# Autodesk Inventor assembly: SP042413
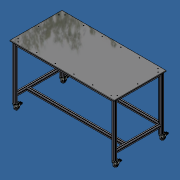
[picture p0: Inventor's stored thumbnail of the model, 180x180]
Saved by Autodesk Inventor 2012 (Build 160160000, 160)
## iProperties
Created: 2013-04
Part Number: SP042413
Document SubType Name: Assembly
Designer: Admin
Author: Admin
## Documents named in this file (7)
- C:\Andys Backup Data\ANDY'S INVENTOR\INVENTOR LIBRARIES\ASSEMBLY LIBRARY\45 SERIES\TABLES_CARTS\SP042413 45X45UL\SP042413 MAIN ASSY.iam
- C:\Andys Backup Data\ANDY'S INVENTOR\INVENTOR LIBRARIES\ASSEMBLY LIBRARY\45 SERIES\TABLES_CARTS\SP042413 45X45UL\SP042413 LEG ASSY.iam
- C:\Andys Backup Data\ANDY'S INVENTOR\INVENTOR LIBRARIES\ASSEMBLY LIBRARY\45 SERIES\TABLES_CARTS\SP042413 45X45UL\SP042413 HORI WIDTH.ipt
- C:\Andys Backup Data\ANDY'S INVENTOR\INVENTOR LIBRARIES\ASSEMBLY LIBRARY\45 SERIES\TABLES_CARTS\SP042413 45X45UL\SP042413 HORI DEPTH.ipt
- C:\Andys Backup Data\ANDY'S INVENTOR\INVENTOR LIBRARIES\ASSEMBLY LIBRARY\45 SERIES\TABLES_CARTS\SP042413 45X45UL\SP042413 TABLE TOP.ipt
- C:\Andys Backup Data\ANDY'S INVENTOR\INVENTOR LIBRARIES\PARTS LIBRARY\FASTENING ELEMENTS\SCREWS COUNTERSUNK\21.1566_9 M6X25 CSUNK BLACK.IPT
- C:\Andys Backup Data\ANDY'S INVENTOR\INVENTOR LIBRARIES\PARTS LIBRARY\FASTENING ELEMENTS\NUTS\21.1330_2 M6 SQUARE NUT POS FXG.ipt
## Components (50 placed, 6 different names)
1. SP042413 LEG ASSY:1 [sub-assembly] — Mate:1, Flush:1, Flush:2, Mate:2, Flush:3, Flush:4, Flush:22
2. SP042413 HORI WIDTH:1 — Mate:1, Flush:1, Flush:2, Mate:16
3. SP042413 HORI DEPTH:1 — Mate:2, Flush:3, Flush:4, Mate:3, Flush:5, Flush:6, Mate:14
4. SP042413 LEG ASSY:2 [sub-assembly] — Mate:3, Flush:5, Flush:6, Mate:4, Flush:7, Flush:8, Mate:9, Mate:10, Flush:17, Flush:24
5. SP042413 HORI WIDTH:2 — Mate:4, Flush:7, Flush:8, Mate:5, Flush:9, Flush:10, Mate:11, Flush:20, Mate:12
6. SP042413 LEG ASSY:3 [sub-assembly] — Mate:5, Flush:9, Flush:10, Mate:6, Flush:11, Flush:12, Mate:8, Flush:15
7. SP042413 HORI DEPTH:2 — Mate:6, Flush:11, Flush:12, Mate:7, Flush:13, Flush:14, Mate:15
8. SP042413 LEG ASSY:4 [sub-assembly] — Mate:7, Flush:13, Flush:14
9. SP042413 HORI DEPTH:3 — Mate:8, Flush:15, Flush:23
10. SP042413 HORI WIDTH:3 — Mate:9, Flush:18, Flush:24
11. SP042413 HORI DEPTH:4 — Mate:10, Flush:17, Flush:18, Mate:13, Flush:21
12. SP042413 HORI DEPTH:5 — Mate:11, Flush:20, Mate:12
13. SP042413 HORI WIDTH:4 — Mate:13, Flush:21, Flush:22, Flush:23
14. SP042413 TABLE TOP:1 — Mate:14, Mate:15, Mate:16, Insert:1, Insert:2, Insert:3, Insert:4, Insert:5, Insert:6, Insert:7, Insert:8, Insert:9, Insert:10, Insert:11, Insert:12, Insert:13, Insert:14, Insert:15, Insert:16, Insert:17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
15. 21.1566/9 M6x25 C'SUNK BLACK:1 — Insert:3
16. 21.1566/9 M6x25 C'SUNK BLACK:2 — Insert:4
17. 21.1566/9 M6x25 C'SUNK BLACK:3 — Insert:5
18. 21.1566/9 M6x25 C'SUNK BLACK:4 — Insert:6
19. 21.1566/9 M6x25 C'SUNK BLACK:5 — Insert:7
20. 21.1566/9 M6x25 C'SUNK BLACK:6 — Insert:8
21. 21.1566/9 M6x25 C'SUNK BLACK:7 — Insert:9
22. 21.1566/9 M6x25 C'SUNK BLACK:8 — Insert:10
23. 21.1566/9 M6x25 C'SUNK BLACK:9 — Insert:11
24. 21.1566/9 M6x25 C'SUNK BLACK:10 — Insert:12
25. 21.1566/9 M6x25 C'SUNK BLACK:11 — Insert:13
26. 21.1566/9 M6x25 C'SUNK BLACK:12 — Insert:14
27. 21.1566/9 M6x25 C'SUNK BLACK:13 — Insert:15
28. 21.1566/9 M6x25 C'SUNK BLACK:14 — Insert:16
29. 21.1566/9 M6x25 C'SUNK BLACK:15 — Insert:17
30. 21.1566/9 M6x25 C'SUNK BLACK:16 — Insert:18
31. 21.1566/9 M6x25 C'SUNK BLACK:17 — Insert:1
32. 21.1566/9 M6x25 C'SUNK BLACK:18 — Insert:2
33. 21.1330_2 M6 SQUARE NUT POS FXG:1 — Insert:24, Angle:13
34. 21.1330_2 M6 SQUARE NUT POS FXG:2 — Insert:23, Angle:14
35. 21.1330_2 M6 SQUARE NUT POS FXG:3 — Insert:22, Angle:15
36. 21.1330_2 M6 SQUARE NUT POS FXG:4 — Insert:21, Angle:16
37. 21.1330_2 M6 SQUARE NUT POS FXG:5 — Insert:19
38. 21.1330_2 M6 SQUARE NUT POS FXG:6 — Insert:20
39. 21.1330_2 M6 SQUARE NUT POS FXG:7 — Insert:25, Angle:12
40. 21.1330_2 M6 SQUARE NUT POS FXG:8 — Insert:26, Angle:11
41. 21.1330_2 M6 SQUARE NUT POS FXG:9 — Insert:27, Angle:10
42. 21.1330_2 M6 SQUARE NUT POS FXG:10 — Insert:28, Angle:9
43. 21.1330_2 M6 SQUARE NUT POS FXG:11 — Insert:29, Angle:8
44. 21.1330_2 M6 SQUARE NUT POS FXG:12 — Insert:30, Angle:7
45. 21.1330_2 M6 SQUARE NUT POS FXG:13 — Insert:31, Angle:6
46. 21.1330_2 M6 SQUARE NUT POS FXG:14 — Insert:32, Angle:5
47. 21.1330_2 M6 SQUARE NUT POS FXG:15 — Insert:33, Angle:4
48. 21.1330_2 M6 SQUARE NUT POS FXG:16 — Insert:36, Angle:1
49. 21.1330_2 M6 SQUARE NUT POS FXG:17 — Insert:35, Angle:2
50. 21.1330_2 M6 SQUARE NUT POS FXG:18 — Insert:34, Angle:3
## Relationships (90: Insert 36, Flush 22, Mate 16, Angle 16)
- Mate:1: SP042413 LEG ASSY:1 ↔ SP042413 HORI WIDTH:1
- Flush:1: SP042413 LEG ASSY:1 ↔ SP042413 HORI WIDTH:1
- Flush:2: SP042413 LEG ASSY:1 ↔ SP042413 HORI WIDTH:1
- Mate:2: SP042413 LEG ASSY:1 ↔ SP042413 HORI DEPTH:1
- Flush:3: SP042413 LEG ASSY:1 ↔ SP042413 HORI DEPTH:1
- Flush:4: SP042413 LEG ASSY:1 ↔ SP042413 HORI DEPTH:1
- Mate:3: SP042413 HORI DEPTH:1 ↔ SP042413 LEG ASSY:2
- Flush:5: SP042413 HORI DEPTH:1 ↔ SP042413 LEG ASSY:2
- Flush:6: SP042413 HORI DEPTH:1 ↔ SP042413 LEG ASSY:2
- Mate:4: SP042413 LEG ASSY:2 ↔ SP042413 HORI WIDTH:2
- Flush:7: SP042413 LEG ASSY:2 ↔ SP042413 HORI WIDTH:2
- Flush:8: SP042413 LEG ASSY:2 ↔ SP042413 HORI WIDTH:2
- Mate:5: SP042413 HORI WIDTH:2 ↔ SP042413 LEG ASSY:3
- Flush:9: SP042413 HORI WIDTH:2 ↔ SP042413 LEG ASSY:3
- Flush:10: SP042413 HORI WIDTH:2 ↔ SP042413 LEG ASSY:3
- Mate:6: SP042413 LEG ASSY:3 ↔ SP042413 HORI DEPTH:2
- Flush:11: SP042413 LEG ASSY:3 ↔ SP042413 HORI DEPTH:2
- Flush:12: SP042413 LEG ASSY:3 ↔ SP042413 HORI DEPTH:2
- Mate:7: SP042413 HORI DEPTH:2 ↔ SP042413 LEG ASSY:4
- Flush:13: SP042413 HORI DEPTH:2 ↔ SP042413 LEG ASSY:4
- Flush:14: SP042413 HORI DEPTH:2 ↔ SP042413 LEG ASSY:4
- Mate:8: SP042413 LEG ASSY:3 ↔ SP042413 HORI DEPTH:3
- Flush:15: SP042413 LEG ASSY:3 ↔ SP042413 HORI DEPTH:3
- Mate:9: SP042413 LEG ASSY:2 ↔ SP042413 HORI WIDTH:3
- Mate:10: SP042413 LEG ASSY:2 ↔ SP042413 HORI DEPTH:4
- Flush:17: SP042413 LEG ASSY:2 ↔ SP042413 HORI DEPTH:4
- Flush:18: SP042413 HORI WIDTH:3 ↔ SP042413 HORI DEPTH:4
- Mate:11: SP042413 HORI WIDTH:2 ↔ SP042413 HORI DEPTH:5
- Flush:20: SP042413 HORI WIDTH:2 ↔ SP042413 HORI DEPTH:5
- Mate:12: SP042413 HORI WIDTH:2 ↔ SP042413 HORI DEPTH:5
- Mate:13: SP042413 HORI DEPTH:4 ↔ SP042413 HORI WIDTH:4
- Flush:21: SP042413 HORI DEPTH:4 ↔ SP042413 HORI WIDTH:4
- Flush:22: SP042413 LEG ASSY:1 ↔ SP042413 HORI WIDTH:4
- Flush:23: SP042413 HORI DEPTH:3 ↔ SP042413 HORI WIDTH:4
- Mate:14: SP042413 HORI DEPTH:1 ↔ SP042413 TABLE TOP:1
- Mate:15: SP042413 HORI DEPTH:2 ↔ SP042413 TABLE TOP:1
- Mate:16: SP042413 HORI WIDTH:1 ↔ SP042413 TABLE TOP:1
- Insert:1: SP042413 TABLE TOP:1 ↔ 21.1566/9 M6x25 C'SUNK BLACK:17
- Insert:2: SP042413 TABLE TOP:1 ↔ 21.1566/9 M6x25 C'SUNK BLACK:18
- Insert:3: SP042413 TABLE TOP:1 ↔ 21.1566/9 M6x25 C'SUNK BLACK:1
- Insert:4: SP042413 TABLE TOP:1 ↔ 21.1566/9 M6x25 C'SUNK BLACK:2
- Insert:5: SP042413 TABLE TOP:1 ↔ 21.1566/9 M6x25 C'SUNK BLACK:3
- Insert:6: SP042413 TABLE TOP:1 ↔ 21.1566/9 M6x25 C'SUNK BLACK:4
- Insert:7: SP042413 TABLE TOP:1 ↔ 21.1566/9 M6x25 C'SUNK BLACK:5
- Insert:8: SP042413 TABLE TOP:1 ↔ 21.1566/9 M6x25 C'SUNK BLACK:6
- Insert:9: SP042413 TABLE TOP:1 ↔ 21.1566/9 M6x25 C'SUNK BLACK:7
- Insert:10: SP042413 TABLE TOP:1 ↔ 21.1566/9 M6x25 C'SUNK BLACK:8
- Insert:11: SP042413 TABLE TOP:1 ↔ 21.1566/9 M6x25 C'SUNK BLACK:9
- Insert:12: SP042413 TABLE TOP:1 ↔ 21.1566/9 M6x25 C'SUNK BLACK:10
- Insert:13: SP042413 TABLE TOP:1 ↔ 21.1566/9 M6x25 C'SUNK BLACK:11
- Insert:14: SP042413 TABLE TOP:1 ↔ 21.1566/9 M6x25 C'SUNK BLACK:12
- Insert:15: SP042413 TABLE TOP:1 ↔ 21.1566/9 M6x25 C'SUNK BLACK:13
- Insert:16: SP042413 TABLE TOP:1 ↔ 21.1566/9 M6x25 C'SUNK BLACK:14
- Insert:17: SP042413 TABLE TOP:1 ↔ 21.1566/9 M6x25 C'SUNK BLACK:15
- Insert:18: SP042413 TABLE TOP:1 ↔ 21.1566/9 M6x25 C'SUNK BLACK:16
- Insert:19: SP042413 TABLE TOP:1 ↔ 21.1330_2 M6 SQUARE NUT POS FXG:5
- Insert:20: SP042413 TABLE TOP:1 ↔ 21.1330_2 M6 SQUARE NUT POS FXG:6
- Insert:21: SP042413 TABLE TOP:1 ↔ 21.1330_2 M6 SQUARE NUT POS FXG:4
- Insert:22: SP042413 TABLE TOP:1 ↔ 21.1330_2 M6 SQUARE NUT POS FXG:3
- Insert:23: SP042413 TABLE TOP:1 ↔ 21.1330_2 M6 SQUARE NUT POS FXG:2
- Insert:24: SP042413 TABLE TOP:1 ↔ 21.1330_2 M6 SQUARE NUT POS FXG:1
- Insert:25: SP042413 TABLE TOP:1 ↔ 21.1330_2 M6 SQUARE NUT POS FXG:7
- Insert:26: SP042413 TABLE TOP:1 ↔ 21.1330_2 M6 SQUARE NUT POS FXG:8
- Insert:27: SP042413 TABLE TOP:1 ↔ 21.1330_2 M6 SQUARE NUT POS FXG:9
- Insert:28: SP042413 TABLE TOP:1 ↔ 21.1330_2 M6 SQUARE NUT POS FXG:10
- Insert:29: SP042413 TABLE TOP:1 ↔ 21.1330_2 M6 SQUARE NUT POS FXG:11
- Insert:30: SP042413 TABLE TOP:1 ↔ 21.1330_2 M6 SQUARE NUT POS FXG:12
- Insert:31: SP042413 TABLE TOP:1 ↔ 21.1330_2 M6 SQUARE NUT POS FXG:13
- Insert:32: SP042413 TABLE TOP:1 ↔ 21.1330_2 M6 SQUARE NUT POS FXG:14
- Insert:33: SP042413 TABLE TOP:1 ↔ 21.1330_2 M6 SQUARE NUT POS FXG:15
- Insert:34: SP042413 TABLE TOP:1 ↔ 21.1330_2 M6 SQUARE NUT POS FXG:18
- Insert:35: SP042413 TABLE TOP:1 ↔ 21.1330_2 M6 SQUARE NUT POS FXG:17
- Insert:36: SP042413 TABLE TOP:1 ↔ 21.1330_2 M6 SQUARE NUT POS FXG:16
- Angle:1: SP042413 TABLE TOP:1 ↔ 21.1330_2 M6 SQUARE NUT POS FXG:16
- Angle:2: SP042413 TABLE TOP:1 ↔ 21.1330_2 M6 SQUARE NUT POS FXG:17
- Angle:3: SP042413 TABLE TOP:1 ↔ 21.1330_2 M6 SQUARE NUT POS FXG:18
- Angle:4: SP042413 TABLE TOP:1 ↔ 21.1330_2 M6 SQUARE NUT POS FXG:15
- Angle:5: SP042413 TABLE TOP:1 ↔ 21.1330_2 M6 SQUARE NUT POS FXG:14
- Angle:6: SP042413 TABLE TOP:1 ↔ 21.1330_2 M6 SQUARE NUT POS FXG:13
- Angle:7: SP042413 TABLE TOP:1 ↔ 21.1330_2 M6 SQUARE NUT POS FXG:12
- Angle:8: SP042413 TABLE TOP:1 ↔ 21.1330_2 M6 SQUARE NUT POS FXG:11
- Angle:9: SP042413 TABLE TOP:1 ↔ 21.1330_2 M6 SQUARE NUT POS FXG:10
- Angle:10: SP042413 TABLE TOP:1 ↔ 21.1330_2 M6 SQUARE NUT POS FXG:9
- Angle:11: SP042413 TABLE TOP:1 ↔ 21.1330_2 M6 SQUARE NUT POS FXG:8
- Angle:12: SP042413 TABLE TOP:1 ↔ 21.1330_2 M6 SQUARE NUT POS FXG:7
- Angle:13: SP042413 TABLE TOP:1 ↔ 21.1330_2 M6 SQUARE NUT POS FXG:1
- Angle:14: SP042413 TABLE TOP:1 ↔ 21.1330_2 M6 SQUARE NUT POS FXG:2
- Angle:15: SP042413 TABLE TOP:1 ↔ 21.1330_2 M6 SQUARE NUT POS FXG:3
- Angle:16: SP042413 TABLE TOP:1 ↔ 21.1330_2 M6 SQUARE NUT POS FXG:4
- Flush:24: SP042413 LEG ASSY:2 ↔ SP042413 HORI WIDTH:3
## Named parameters: Height = 1066.8 mm, Width = 1828.8 mm, DEPTH = 914.4 mm, LOWER_INSET = 203.2 mm, TABLE_TOP_THICKNESS = 12.7 mm, LEVELER_HEIGHT = 115.824 mm, TOP_OVERHANG = 25.4 mm
